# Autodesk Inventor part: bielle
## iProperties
Shininess: 100.0
Length Units: 11269
Angle Units: 11279
Time Units: 11290
Mass Units: 11283
Length Display Precision: 3
Angle Display Precision: 2
Compacted: True
Created: 2001-12
Part Number: bielle
Material: Par défaut
Document SubType Name: Modélisation
Designer: pichon
Density: 0.0
Volumn: 0.0
Area: 0.0
PropertySet Name: Model Information
Control State: 0
Master: False
Checked Out: False
Author: pichon
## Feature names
1. Extrusion1
